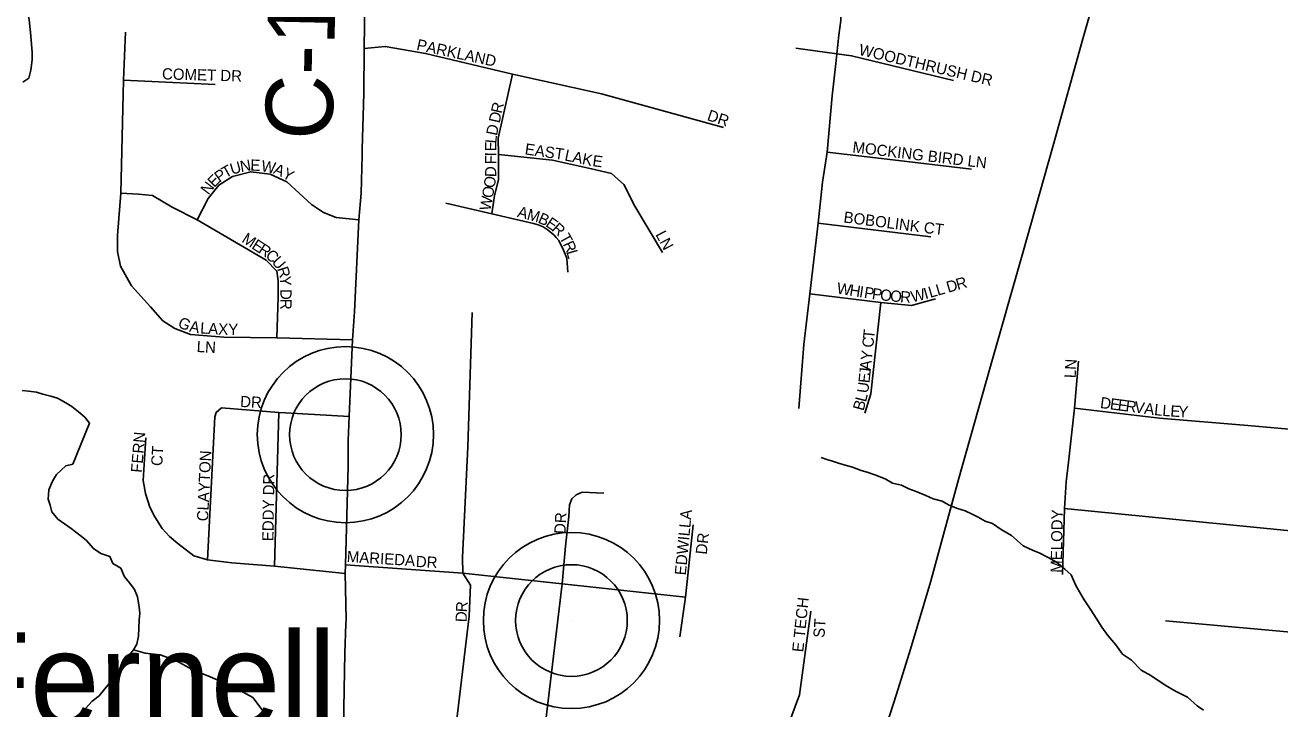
# Model space of a CAD drawing. Extents: x 1310247 to 1664935, y 235267 to 584339.
# Drawn here: x 1459518 to 1465113, y 408689 to 411738 of the extents above; entities that cross this region are included whole.
import ezdxf

# ---------------------------------------------------------------- set-up
doc = ezdxf.new("R2010")
doc.units = 0
for name, color, linetype in [('GM_X_County_Road', 7, 'Continuous'), ('GM_X_County_Road_Text', 7, 'Continuous'), ('GM_X_Interstate_Route', 7, 'Continuous'), ('GM_X_Minor_River', 7, 'Continuous'), ('GM_X_Township_Subdivision', 7, 'Continuous'), ('GM_X_Township_Subdivision_Text', 7, 'Continuous'), ('GM_X_Unincorporated', 7, 'Continuous'), ('GM_X_Unincorporated_Location', 7, 'Continuous'), ('GM_X_Unincorporated_Text', 7, 'Continuous')]:
    doc.layers.add(name, color=color, linetype=linetype)

msp = doc.modelspace()

# ---------------------------------------------------------------- linework, layer by layer
at = {"layer": 'GM_X_County_Road'}
for points in [[(1461020.6, 411157.3), (1461021.3, 411185), (1461027.8, 411433.5), (1461029.8, 411633), (1461037.6, 412159.4), (1461031.3, 412463.9)], [(1460948.4, 409068.4), (1460949.1, 409088.7), (1460945.8, 409292.1), (1460947.2, 409331.9), (1460959.1, 409771.8), (1460959.1, 409885.9), (1460963.6, 409992.4), (1460977.3, 410334.6), (1460986.4, 410459.3), (1461006.6, 410869.5), (1461016.4, 410988.8), (1461020.6, 411157.3)], [(1460916.9, 407448.5), (1460932.2, 408029.2), (1460928.2, 408215.3), (1460936.2, 408528.1), (1460944.1, 408937.9), (1460948.4, 409068.4)]]:
    msp.add_lwpolyline(points, dxfattribs=at)
at = {"layer": 'GM_X_Interstate_Route'}
msp.add_lwpolyline([(1465163.7, 414166.3), (1465029.3, 413917.9), (1464934.6, 413720.4), (1464863.5, 413572.2), (1464809, 413437.6), (1464726.8, 413253.6), (1464649.5, 413037.4), (1464559.1, 412789.6), (1464482.8, 412543.3), (1464367.4, 412145.7), (1464233.7, 411676.5), (1464101.7, 411201.2), (1463963.2, 410712.1), (1463822.6, 410217.1), (1463679.6, 409712), (1463554.2, 409254.6), (1463466.1, 408954.5), (1463403.4, 408753.9), (1463345.4, 408575.2)], dxfattribs=at)
at = {"layer": 'GM_X_Minor_River'}
for points in [[(1459558, 412235.4), (1459575.2, 412206.8), (1459588.5, 412176.3), (1459597.7, 412146), (1459596.6, 412103.9), (1459589.6, 412063.9), (1459582.9, 412038), (1459572.2, 412012.2), (1459559.1, 411968.3), (1459548.4, 411942.5), (1459543.4, 411902.5), (1459530.6, 411872.7), (1459525.7, 411838.8), (1459526.8, 411802.6), (1459535.7, 411762.2), (1459539, 411732), (1459542.3, 411705.8), (1459550, 411615.3), (1459549.1, 411583.2), (1459543.9, 411537.2), (1459535, 411501.3), (1459508.6, 411483.9)], [(1459505.1, 410108.9), (1459533, 410106.2), (1459568.9, 410101.2), (1459596.7, 410092.5), (1459632.5, 410083.5), (1459662.3, 410074.7), (1459699.8, 410053.6), (1459727.3, 410036.8), (1459756.7, 410014), (1459784.1, 409989.2), (1459805.4, 409962.5), (1459730.7, 409779.8), (1459700.5, 409772.6), (1459657.5, 409733.6), (1459640.7, 409703.9), (1459623.7, 409666.2), (1459620.6, 409624.1), (1459629.9, 409597.8), (1459637.2, 409567.5), (1459664.3, 409534.6), (1459723.3, 409493), (1459762.6, 409463.8), (1459790, 409441), (1459823, 409404), (1459856.5, 409381.1), (1459896.2, 409368), (1459909.4, 409337.5), (1459944.8, 409316.5), (1459961.9, 409277.9), (1459985.1, 409249.2), (1460006.4, 409220.5), (1460019.6, 409188.1), (1460026.4, 409141.7), (1460029.7, 409115.5)], [(1464771.9, 408683.2), (1464744.1, 408701.8), (1464700.6, 408740.7), (1464646.9, 408767.7), (1464601.2, 408794.6), (1464537.7, 408837.9), (1464493.9, 408860.8), (1464450.5, 408905.7), (1464410.8, 408932.5), (1464381.4, 408975.2), (1464346, 409016), (1464318.5, 409052.7), (1464293.1, 409093.3), (1464269.6, 409129.8), (1464240.2, 409174.5), (1464224.6, 409200.9), (1464203.2, 409239.5), (1464181.9, 409286), (1464154.2, 409312.6), (1464116.6, 409343.4), (1464078.8, 409364.1), (1464039, 409384.9), (1464013.1, 409395.4), (1463967.3, 409416.3), (1463915.9, 409461.4), (1463870.2, 409488.3), (1463830.5, 409515.1), (1463798.5, 409525.7), (1463766.7, 409544.3), (1463740.8, 409556.8), (1463709, 409571.5), (1463671, 409584.2), (1463635.2, 409598.9), (1463607.3, 409615.4), (1463567.4, 409626.2), (1463533.5, 409640.8), (1463491.6, 409657.6), (1463457.7, 409670.3), (1463425.9, 409686.9), (1463385.9, 409695.6), (1463352.1, 409714.3), (1463306.2, 409733.2), (1463272.3, 409743.8), (1463246.3, 409752.3), (1463206.4, 409767.1), (1463174.4, 409775.7), (1463144.5, 409784.2), (1463118.5, 409792.7), (1463092.6, 409801.2), (1463067, 409809.8)], [(1460029.7, 409115.5), (1460026.9, 409085.5), (1460023.1, 409013.3), (1460016.1, 408977.4), (1460001.5, 408951.7), (1459980.8, 408926.1), (1459966, 408896.4), (1459941.3, 408866.9), (1459920.5, 408837.4), (1459893.6, 408802), (1459848.1, 408746.9), (1459817.5, 408723.7), (1459788.7, 408692.3), (1459753.8, 408659.1)], [(1460001.8, 408952.2), (1460052.9, 408937.9), (1460121, 408930.5), (1460190.7, 408905), (1460266, 408863.3), (1460343.6, 408831.6), (1460409.2, 408804.2), (1460474.8, 408772.8), (1460534.2, 408739.5), (1460588.9, 408666.1)]]:
    msp.add_lwpolyline(points, dxfattribs=at)
at = {"layer": 'GM_X_Township_Subdivision'}
for points in [[(1463134.1, 411580.2), (1463137.5, 411609.6), (1463146.5, 411692.6), (1463154.6, 411758.4), (1463151.9, 411826), (1463119.5, 411901.7), (1463081.6, 411963.9), (1463063.6, 412017.1), (1463059.1, 412065.7), (1463067.2, 412141.5), (1463158.2, 412917.8), (1463165.7, 413010)], [(1459965.1, 411706.6), (1459956.9, 411492.4), (1459945.4, 410988.8), (1459930.7, 410799.1), (1459930.7, 410728.8), (1459943.8, 410663.5), (1459992.8, 410575.1), (1460077.9, 410482), (1460131.8, 410419.8), (1460185.8, 410385.5), (1460256.1, 410357.7), (1460404.9, 410346.3), (1460640.3, 410343), (1460977.3, 410334.6)], [(1461029.8, 411633), (1461123.6, 411642.8), (1461303.8, 411611.4), (1461691.6, 411519.4), (1462088.3, 411431.3), (1462631.7, 411281.6)], [(1462954.5, 411634.9), (1463137.5, 411609.6), (1463203.3, 411601.5), (1463657.6, 411490.7)], [(1462967.9, 410027.7), (1462990.4, 410314.1), (1463017.4, 410539.8), (1463054.2, 410854.5), (1463073, 411037), (1463094.2, 411170.9), (1463115.9, 411422.2), (1463134.1, 411580.2)], [(1459956.9, 411492.4), (1460051.7, 411487.5), (1460365.6, 411472.8)], [(1461598.7, 410896.2), (1461611.3, 410978.7), (1461628.2, 411047.3), (1461628.2, 411160.3), (1461627, 411233.4), (1461691.6, 411519.4)], [(1461628.2, 411160.3), (1461869.3, 411135.2), (1462043.7, 411097.5), (1462132.4, 411076.7), (1462187.2, 411027.7), (1462236.2, 410929.8), (1462359.6, 410724.1)], [(1463094.2, 411170.9), (1463361.9, 411139.6), (1463737.1, 411095.8)], [(1460285.5, 410869.5), (1460334.6, 410964.3), (1460381.3, 411024.6), (1460442.5, 411062.4), (1460524.2, 411083.6), (1460610.9, 411073.8), (1460684.4, 411039.5), (1460795.6, 410938.1), (1460848, 410902.1), (1460905.2, 410879.3), (1461006.6, 410869.5)], [(1460640.3, 410343), (1460646.8, 410526.1), (1460646.8, 410598), (1460640.3, 410640.6), (1460592.9, 410689.6), (1460285.5, 410869.5), (1460174.3, 410926.7), (1460086.1, 410977.4), (1460023.9, 410983.9), (1459945.4, 410988.8)], [(1461393.9, 410943.5), (1461598.7, 410896.2), (1461784.6, 410853.2), (1461805.9, 410846.8), (1461827.3, 410837.9), (1461845.5, 410826.5), (1461859.5, 410816.7), (1461875.3, 410803), (1461886.4, 410791.4), (1461897.5, 410777.4), (1461918.8, 410735), (1461933.6, 410698.6), (1461937.5, 410636.9)], [(1463054.2, 410854.5), (1463555.7, 410794.4)], [(1463017.4, 410539.8), (1463333.1, 410500.5), (1463470.7, 410488), (1463577, 410518)], [(1463261.8, 410007.7), (1463288.1, 410094), (1463333.1, 410500.5)], [(1461389.9, 407554.7), (1461390.2, 408125.5), (1461407.1, 408346), (1461497.5, 409102.5), (1461503.6, 409240.9), (1461470.1, 409294.2), (1461468.6, 409364.1), (1461491.4, 409857), (1461511.2, 410456.3)], [(1464170.1, 409789.6), (1464196.7, 410029.7), (1464215, 410239.7)], [(1460331, 409352.9), (1460363.6, 409991.1), (1460369.9, 410011), (1460394.3, 410030.7), (1460649.1, 410010.6), (1460678.7, 410008.3), (1460963.6, 409992.4)], [(1460630.1, 409325.1), (1460649.1, 410010.6)], [(1464196.7, 410029.7), (1464575.5, 409984.6), (1464969.7, 409952), (1465287.2, 409924.2), (1465693.8, 409883), (1466043.8, 409850.4), (1466094.7, 409840.8), (1466135.9, 409820.6), (1466175.2, 409800.5), (1466221.2, 409772.7), (1466274, 409754.5), (1466386.2, 409741)], [(1460056.2, 409897.4), (1460044.2, 409706.8), (1460055, 409649.7), (1460075, 409587.9), (1460096.7, 409544.7), (1460129.1, 409493.8), (1460161.5, 409458.2), (1460198.6, 409425.8), (1460270.8, 409372), (1460331, 409352.9), (1460440.1, 409340.4), (1460630.1, 409325.1), (1460945.8, 409292.1)], [(1464146.9, 409388.4), (1464152.6, 409582.8), (1464160.3, 409700.8), (1464170.1, 409789.6)], [(1461719.2, 407634.3), (1461912.8, 409247), (1461928.2, 409414.6), (1461941.8, 409546.5), (1461946, 409598.9), (1461955.4, 409626.1), (1461975.3, 409643.8), (1462001.5, 409655.3), (1462097.8, 409650.1)], [(1466348.5, 409365.3), (1464152.6, 409582.8)], [(1462437.9, 409009.6), (1462463, 409187.5), (1462496.5, 409509.9)], [(1464143.9, 409287.9), (1464146.9, 409388.4)], [(1460947.2, 409331.9), (1461470.1, 409294.2), (1461912.8, 409247), (1462463, 409187.5)], [(1462767.4, 407836.8), (1462818, 408259.4), (1462850.1, 408427.4), (1462971.2, 408751.2), (1463020.6, 409124.3)], [(1466182.6, 408938.4), (1464602.4, 409081)]]:
    msp.add_lwpolyline(points, dxfattribs=at)
at = {"layer": 'GM_X_Unincorporated'}
for centre, radius in [((1460946.2, 409911.7), 392.8), ((1460946.2, 409911.7), 249), ((1461954, 409082.9), 392.8), ((1461954, 409082.9), 249)]:
    msp.add_circle(centre, radius, dxfattribs=at)
at = {"layer": 'GM_X_Unincorporated_Location'}
for p, q in [((1460946.2, 409911.7), (1460946.2, 409911.7)), ((1461954, 409082.9), (1461954, 409082.9))]:
    msp.add_line(p, q, dxfattribs=at)

# ---------------------------------------------------------------- texts
at = {"layer": 'GM_X_County_Road_Text'}
msp.add_text('C-154', height=300, rotation=88.7197, dxfattribs=at).set_placement((1460887.8, 411223.3))
at = {"layer": 'GM_X_Township_Subdivision_Text'}
for s, rotation, p in [('PARKLAND', 347.7977, (1461260.3, 411627.7)), ('WOODTHRUSH DR', 346.7595, (1463232, 411605.8)), ('COMET DR', 358.3873, (1460128.1, 411496)), ('R', 77.4815, (1461643, 411341.2)), ('DR', 341.5614, (1462555.2, 411314.9)), ('D', 77.4641, (1461633.5, 411298.3)), ('L', 85.1025, (1461619, 411208.9)), ('D', 78.4243, (1461621.8, 411242.5)), ('E', 89.8823, (1461619, 411174.8)), ('EAST', 351.876, (1461743.9, 411161.5)), ('MOCKING BIRD LN', 353.1574, (1463205, 411170.3)), ('U', 15.9664, (1460440, 411070.1)), ('N', 9.6168, (1460480.8, 411081.9)), ('E', 358.0872, (1460521.6, 411089)), ('W', 349.6891, (1460568, 411086.9)), ('F', 89.8574, (1461618.9, 411117.6)), ('I', 89.8655, (1461619, 411152.8)), ('L', 347.972, (1461920.6, 411135)), ('A', 347.9571, (1461955.1, 411127.6)), ('K', 348.6557, (1461998.7, 411118.3)), ('E', 352.6807, (1462045.7, 411109.1)), ('E', 44.9034, (1460361.3, 411011)), ('P', 35.471, (1460384.6, 411034.5)), ('T', 29.1316, (1460412, 411054.1)), ('A', 336.3681, (1460621.3, 411077.5)), ('Y', 330.8541, (1460660.5, 411060.4)), ('D', 89.2045, (1461618.3, 411059.8)), ('N', 52.7192, (1460335.9, 410977.4)), ('O', 79.4918, (1461603, 410963.8)), ('O', 81.8179, (1461611.4, 411009.2)), ('W', 79.4846, (1461592.6, 410907.5)), ('A', 344.58, (1461709.7, 410883.5)), ('M', 344.5675, (1461752.1, 410871.8)), ('BOBOLINK CT', 352.6492, (1463165.1, 410857.9)), ('B', 335.8797, (1461801.2, 410858.4)), ('E', 325.9841, (1461835.3, 410843.3)), ('R', 317.5075, (1461862.9, 410824.9)), ('M', 327.1181, (1460480.4, 410773.1)), ('T', 298.7893, (1461898.2, 410791.6)), ('LN', 297.8914, (1462327.4, 410804.6)), ('E', 327.1282, (1460524.7, 410744.4)), ('R', 327.1116, (1460554.3, 410725.3)), ('R', 294.458, (1461914.7, 410761.6)), ('C', 319.5383, (1460586.1, 410704.8)), ('U', 310.5444, (1460614.8, 410680.6)), ('L', 286.5422, (1461930.5, 410727.3)), ('R', 288.0203, (1460640.9, 410651.7)), ('Y', 274.7038, (1460652.5, 410617)), ('W', 351.1733, (1463134.5, 410541.1)), ('H', 351.1715, (1463191, 410532.3)), ('I', 351.1747, (1463234.5, 410525.6)), ('P', 351.1777, (1463256.2, 410522.2)), ('L', 16.0843, (1463553.4, 410521.1)), ('L', 16.058, (1463587.2, 410530.8)), ('D', 16.0703, (1463633.7, 410544.2)), ('R', 16.0926, (1463676, 410556.4)), ('D', 270.1749, (1460656.3, 410561)), ('P', 351.5906, (1463291.4, 410516.8)), ('O', 353.8644, (1463328.4, 410511.3)), ('O', 354.9472, (1463373.2, 410506.5)), ('R', 356.1646, (1463418.2, 410502.6)), ('W', 13.1151, (1463473.7, 410501.2)), ('I', 16.2087, (1463532.2, 410514.9)), ('R', 270, (1460656.5, 410517.1)), ('G', 336.0264, (1460195.5, 410393.4)), ('A', 349.5348, (1460248, 410371.7)), ('L', 356.3048, (1460297.7, 410363)), ('A', 356.694, (1460333.2, 410360.7)), ('X', 357.9211, (1460378.3, 410358.1)), ('Y', 359.9253, (1460424.1, 410356.5)), ('C', 84.0511, (1463299.1, 410297.5)), ('T', 84.0339, (1463303.2, 410336.8)), ('LN', 356.989, (1460282.3, 410280.2)), ('A', 84.0219, (1463288.5, 410196.8)), ('Y', 84.0561, (1463293.1, 410240.6)), ('LN', 86.8215, (1464201.7, 410162.7)), ('E', 84.0454, (1463282.6, 410139.8)), ('J', 84.071, (1463286.3, 410174.9)), ('U', 82.3052, (1463276.5, 410094.6)), ('DR', 356.9884, (1460476, 410035.2)), ('B', 74.6618, (1463256, 410015.2)), ('L', 75.8357, (1463266.7, 410054.4)), ('D', 352.5469, (1464309.1, 410030.7)), ('E', 352.5462, (1464352.7, 410025)), ('E', 352.5462, (1464387.6, 410020.5)), ('R', 352.5466, (1464422.5, 410015.9)), ('V', 352.5469, (1464461.7, 410010.8)), ('A', 352.5469, (1464505.4, 410005)), ('L', 353.7902, (1464550.2, 409999.2)), ('L', 355.9756, (1464587.2, 409995.2)), ('E', 356.418, (1464622.8, 409992.7)), ('Y', 356.4348, (1464657.9, 409990.5)), ('FERN', 85.2389, (1460039.3, 409740.6)), ('CT', 86.8222, (1460129.6, 409770.8)), ('CLAYTON', 87.3955, (1460334, 409524.6)), ('EDDY DR', 89.0613, (1460625.1, 409436.3)), ('EDWILLA', 84.5592, (1462463.7, 409283.1)), ('MELODY', 89.0295, (1464140, 409295.6)), ('DR', 86.8101, (1461926.9, 409467.5)), ('DR', 83.9832, (1462557.1, 409375.5)), ('MARIEDA', 356.4773, (1460951.2, 409343.8)), ('DR', 356.989, (1461259.1, 409321.8)), ('E TECH', 84.0519, (1462987.3, 408940)), ('D', 88.2729, (1461486.9, 409075)), ('R', 86.4767, (1461488.2, 409118.6)), ('ST', 86.4118, (1463081.9, 409004.6))]:
    msp.add_text(s, height=50, rotation=rotation, dxfattribs=at).set_placement(p)
at = {"layer": 'GM_X_Unincorporated_Text'}
msp.add_text('Fernell', height=417, rotation=0, dxfattribs=at).set_placement((1459199.5, 408613.2))

doc.saveas('drawing.dxf')
